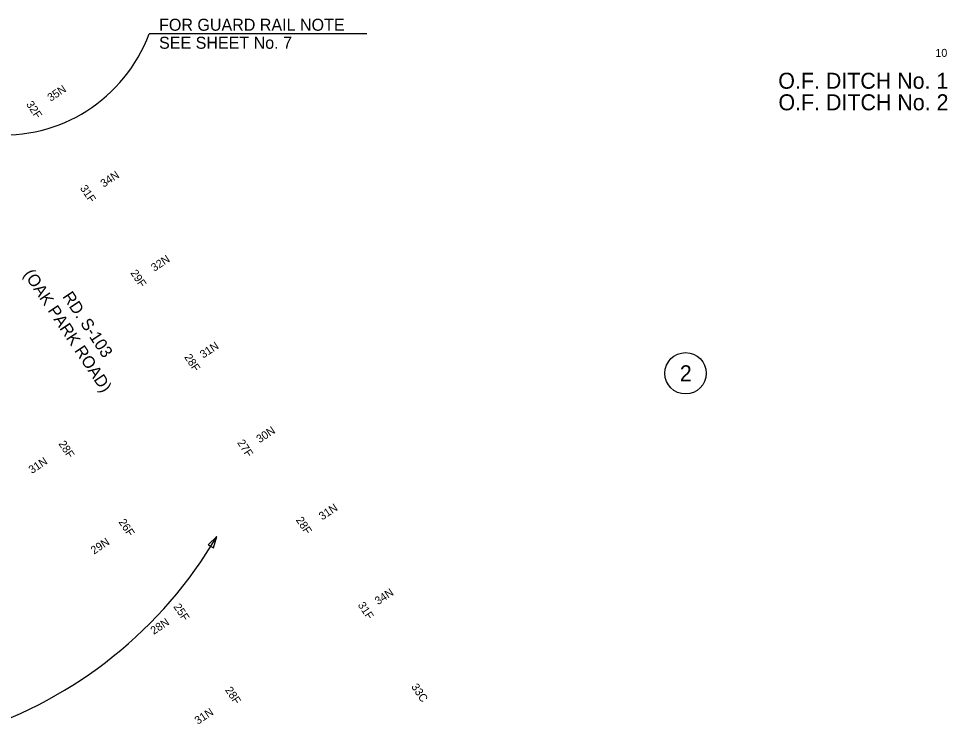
# Model space of a CAD drawing. Extents: x 1964849 to 1967422, y 1116563 to 1122210.
# Drawn here: x 1966944.5 to 1967408.7, y 1121844.8 to 1122201.3 of the extents above; entities that cross this region are included whole.
import ezdxf

# ---------------------------------------------------------------- set-up
doc = ezdxf.new("R2010")
doc.units = 0
for name, color, linetype in [('RD_EX_DV_TX_Prop', 7, 'Continuous'), ('RD_HC_Data', 7, 'Continuous'), ('RD_PD_TX_CstnLmt', 7, 'Continuous'), ('RD_SHT_TX', 7, 'Continuous'), ('RD_TX_Drainage', 7, 'Continuous'), ('RD_TX_Misc1', 7, 'Continuous'), ('RD_TX_RoadID', 7, 'Continuous')]:
    doc.layers.add(name, color=color, linetype=linetype)

msp = doc.modelspace()

# ---------------------------------------------------------------- linework, layer by layer
at = {"layer": 'RD_EX_DV_TX_Prop'}
msp.add_circle((1967277.83, 1122023.9), 10.35, dxfattribs=at)
at = {"layer": 'RD_HC_Data'}
msp.add_lwpolyline([(1967041.94, 1121936.54), (1967043.53, 1121942.33), (1967039.26, 1121938.11)], close=True, dxfattribs=at)
msp.add_arc((1966854.98, 1122052.8), 218.53, 287.8676, 329.6328, dxfattribs=at)
at = {"layer": 'RD_TX_Misc1'}
msp.add_line((1967118.61, 1122193.69), (1967009.68, 1122193.69), dxfattribs=at)
msp.add_arc((1966936.78, 1122220.78), 77.77, 265.305, 339.6154, dxfattribs=at)

# ---------------------------------------------------------------- texts
at = {"layer": 'RD_EX_DV_TX_Prop'}
msp.add_text('2', height=8, dxfattribs=at).set_placement((1967275, 1122019.91))
at = {"layer": 'RD_PD_TX_CstnLmt'}
for s, p in [('32F', (1966948.05, 1122158.45)), ('31F', (1966974.99, 1122116.47)), ('29F', (1967000.18, 1122074.11)), ('28F', (1967027.13, 1122031.98)), ('28F', (1966964.24, 1121988.64)), ('27F', (1967053.57, 1121989.22)), ('26F', (1966994.28, 1121949.53)), ('28F', (1967082.88, 1121950.58)), ('25F', (1967021.71, 1121907.22)), ('31F', (1967113.85, 1121908)), ('33C', (1967140.56, 1121867.18)), ('28F', (1967047.49, 1121865.58))]:
    msp.add_text(s, height=4, rotation=303.6494, dxfattribs=at).set_placement(p)
at = {"layer": 'RD_SHT_TX'}
for s, height, p in [('10', 4, (1967402.72, 1122182.13)), ('O.F. DITCH No. 1', 8, (1967324.2, 1122166.19)), ('O.F. DITCH No. 2', 8, (1967324.28, 1122155.41))]:
    msp.add_text(s, height=height, dxfattribs=at).set_placement(p)
at = {"layer": 'RD_TX_Drainage'}
for s, p in [('35N', (1966960.52, 1122159.63)), ('34N', (1966987.03, 1122116.68)), ('32N', (1967012.31, 1122074.61)), ('31N', (1967036.75, 1122031.2)), ('30N', (1967064.95, 1121988.88)), ('31N', (1966951.12, 1121973.51)), ('31N', (1967096.19, 1121950.28)), ('29N', (1966982.15, 1121933.2)), ('34N', (1967124.14, 1121907.91)), ('28N', (1967012.03, 1121893.06)), ('31N', (1967034.11, 1121848.1))]:
    msp.add_text(s, height=4, rotation=33.6494, dxfattribs=at).set_placement(p)
at = {"layer": 'RD_TX_Misc1'}
for s, p in [('FOR GUARD RAIL NOTE', (1967014.68, 1122195.19)), ('SEE SHEET No. 7', (1967014.68, 1122186.19))]:
    msp.add_text(s, height=6, dxfattribs=at).set_placement(p)
at = {"layer": 'RD_TX_RoadID'}
for s, p in [('(OAK PARK ROAD)', (1966946.68, 1122073.51)), ('RD. S-103 ', (1966966.16, 1122062.28))]:
    msp.add_text(s, height=6, rotation=303.6494, dxfattribs=at).set_placement(p)

doc.saveas('drawing.dxf')
